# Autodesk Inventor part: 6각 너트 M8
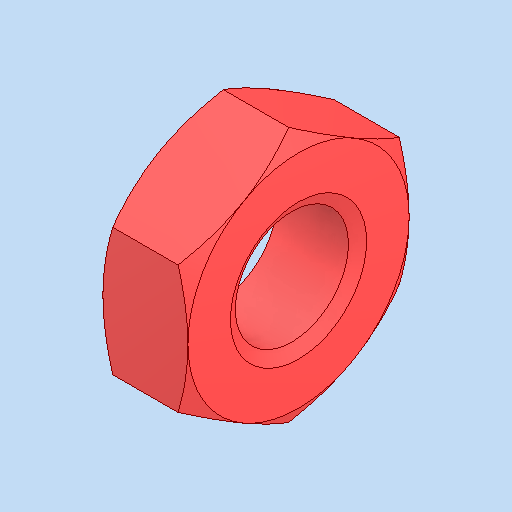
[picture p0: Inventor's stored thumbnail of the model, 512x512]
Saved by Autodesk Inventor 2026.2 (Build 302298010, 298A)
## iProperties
Created: 2026-08
Part Number: 6각 너트 M8
Material: 강철, 연강
Description: 6각 너트
Document SubType Name: Modeling
Designer: PC-2-06
Density: 7.85 g/cm^3
Appearance: 기본값
Author: jhkim
Sending System: Autodesk Inventor 2027
Preprocessor: ST-DEVELOPER v20.1
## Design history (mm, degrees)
feature "Solid1"
node "솔리드1"
